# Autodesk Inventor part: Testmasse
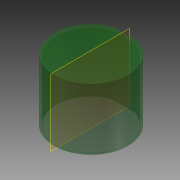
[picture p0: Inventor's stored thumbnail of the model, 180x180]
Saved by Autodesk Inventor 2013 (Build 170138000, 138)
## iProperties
Created: 2012-07
Part Number: Testmasse
Material: Allgemein
Document SubType Name: Modeling
Designer: rYan
Density: 1 g/cm^3
Mass: 524.009 g
Surface Area: 2124.25 cm^2
Volume: 524.009 cm^3
Author: rYan
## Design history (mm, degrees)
sketch "Skizze1"
  geometry: L1 (0, 120)-(0, -125) reference; L2 (-126, 0)-(126, 0) reference; L3 (-29.58, 85)-(29.58, 85); A1 r 90 centre (0, 0) between (-29.58, 85) and (29.58, 85); 1 further point
  constraints: 2 end point, 2 point on circle, 1 centre point, 1 coincident, 1 parallel
  dimensions: "d0" = 180 diameter of A1; "d1" = 85 distance between parallel lines of L2 L3
extrude "Extrusion1" new body sketch "Skizze1" distance "d2" = 150; taper "d3" = 0 deg
feature "Wandstärke1" dims "d4" = 5
workplane "Arbeitsebene1"
node "Volumenkörper1"
other parameters: "d5" = 0
